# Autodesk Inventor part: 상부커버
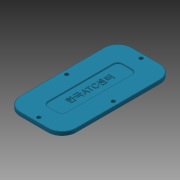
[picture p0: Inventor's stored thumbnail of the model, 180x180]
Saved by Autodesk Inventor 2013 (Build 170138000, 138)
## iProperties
Created: 2016-02
Part Number: 상부커버
Material: 강철, 연강
Document SubType Name: Modeling
Designer: mduedu
Density: 1 g/cm^3
Mass: 15.5198 g
Surface Area: 149.263 cm^2
Volume: 15.5198 cm^3
Author: mduedu
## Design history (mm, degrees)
sketch "스케치1"
  geometry: L1 (30, 60)-(-30, 60); L2 (-30, 60)-(-30, -60); L3 (-30, -60)-(30, -60); L4 (30, -60)-(30, 60); L5 (30, 60)-(-30, -60); L6 (-30, 60)-(30, -60); 1 further point
  constraints: 12 end point, 2 midpoint, 2 parallel, 1 horizontal, 1 perpendicular
  dimensions: "d0" = 60 distance of L2.end L3.end; "d2" = 120 distance of L1.end L2.end
extrude "돌출1" new body sketch "스케치1" distance "d3" = 4; taper "d4" = 0 deg
fillet "모깎기1" dims "d5" = 15
sketch "스케치2"
  geometry: L1 (30, 45)-(30, -45) reference; L2 (15, -60)-(-15, -60) reference; L3 (-30, -45)-(-30, 45) reference; L4 (-15, 60)-(15, 60) reference; L5 (25, 45)-(25, -45); L6 (15, -55)-(-15, -55); L7 (-25, -45)-(-25, 45); L8 (-15, 55)-(15, 55); A1 r 15 centre (15, 45) between (30, 45) and (15, 60) reference; A2 r 15 centre (15, -45) between (15, -60) and (30, -45) reference; A3 r 15 centre (-15, -45) between (-30, -45) and (-15, -60) reference; A4 r 15 centre (-15, 45) between (-15, 60) and (-30, 45) reference; A5 r 10 centre (15, 45) between (25, 45) and (15, 55); A6 r 10 centre (15, -45) between (15, -55) and (25, -45); A7 r 10 centre (-15, -45) between (-25, -45) and (-15, -55); A8 r 10 centre (-15, 45) between (-15, 55) and (-25, 45); 4 further points
  constraints: 8 end point, 8 point on circle, 4 centre point, 4 midpoint, 7 other
  dimensions: "d8" = 5 distance between parallel lines of L7 L3
hole "구멍1" sketch "스케치2" at (0, 55), (25, 0), (0, -55), (-25, 0) diameter "d9" = 4; stored, may be unused: countersink angle "d13" = 90 deg, drill point angle "d15" = 118 deg; dims "d10" = 6, "d11" = 4, "d12" = 2, "d14" = 8
sketch "스케치3"
  geometry: L1 (10, -40)-(-10, -40); L2 (-10, -40)-(-10, 40); L3 (-10, 40)-(10, 40); L4 (10, 40)-(10, -40); L5 (10, -40)-(-10, 40); L6 (-10, -40)-(10, 40); 1 further point
  constraints: 12 end point, 2 midpoint, 2 parallel, 1 horizontal, 1 perpendicular
  dimensions: "d16" = 80 distance of L1.end L2.end; "d18" = 20 distance of L2.end L3.end
extrude "돌출2" cut sketch "스케치3" distance "d19" = 1; taper "d20" = 0 deg
fillet "모깎기2" dims "d21" = 5
fillet "모깎기3" dims "d22" = 0.3
fillet "모깎기4" dims "d23" = 0.3
sketch "스케치4"
  geometry: 2 further points
  constraints: 1 coincident, 1 other
feature "엠보싱1" sketch "스케치4" dims "d0" = 60, "d2" = 120, "d11" = 4, "d24" = 0.5, "d25" = 0
node "솔리드1"
node "절단 모서리 투영1"
